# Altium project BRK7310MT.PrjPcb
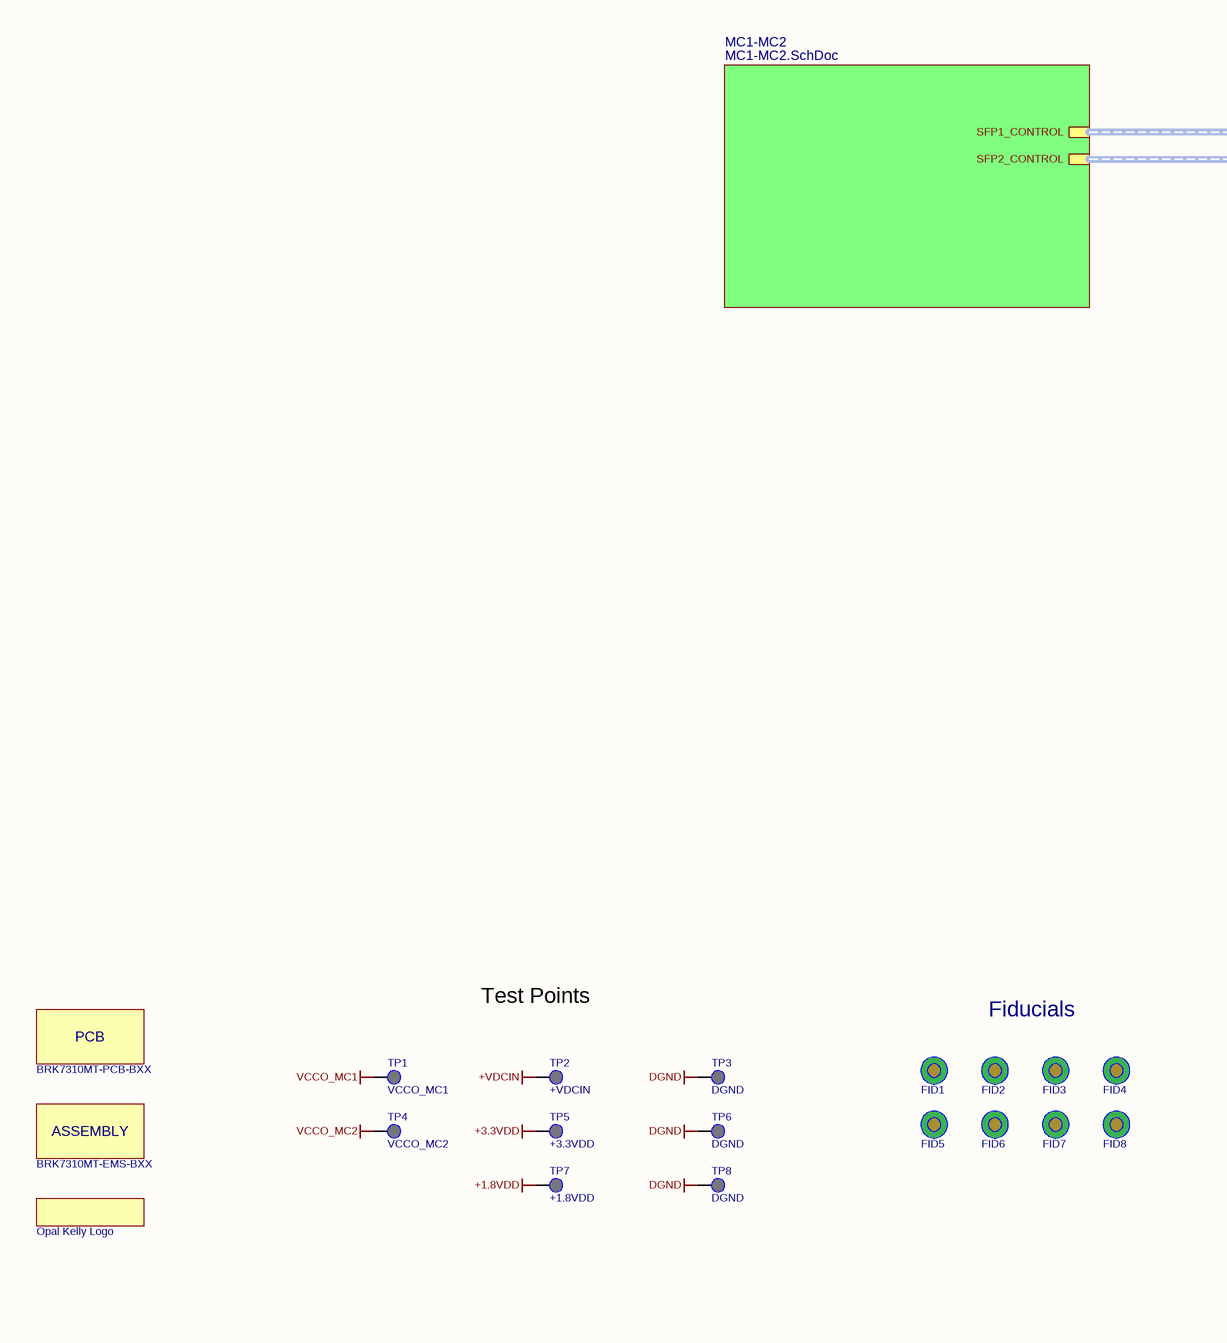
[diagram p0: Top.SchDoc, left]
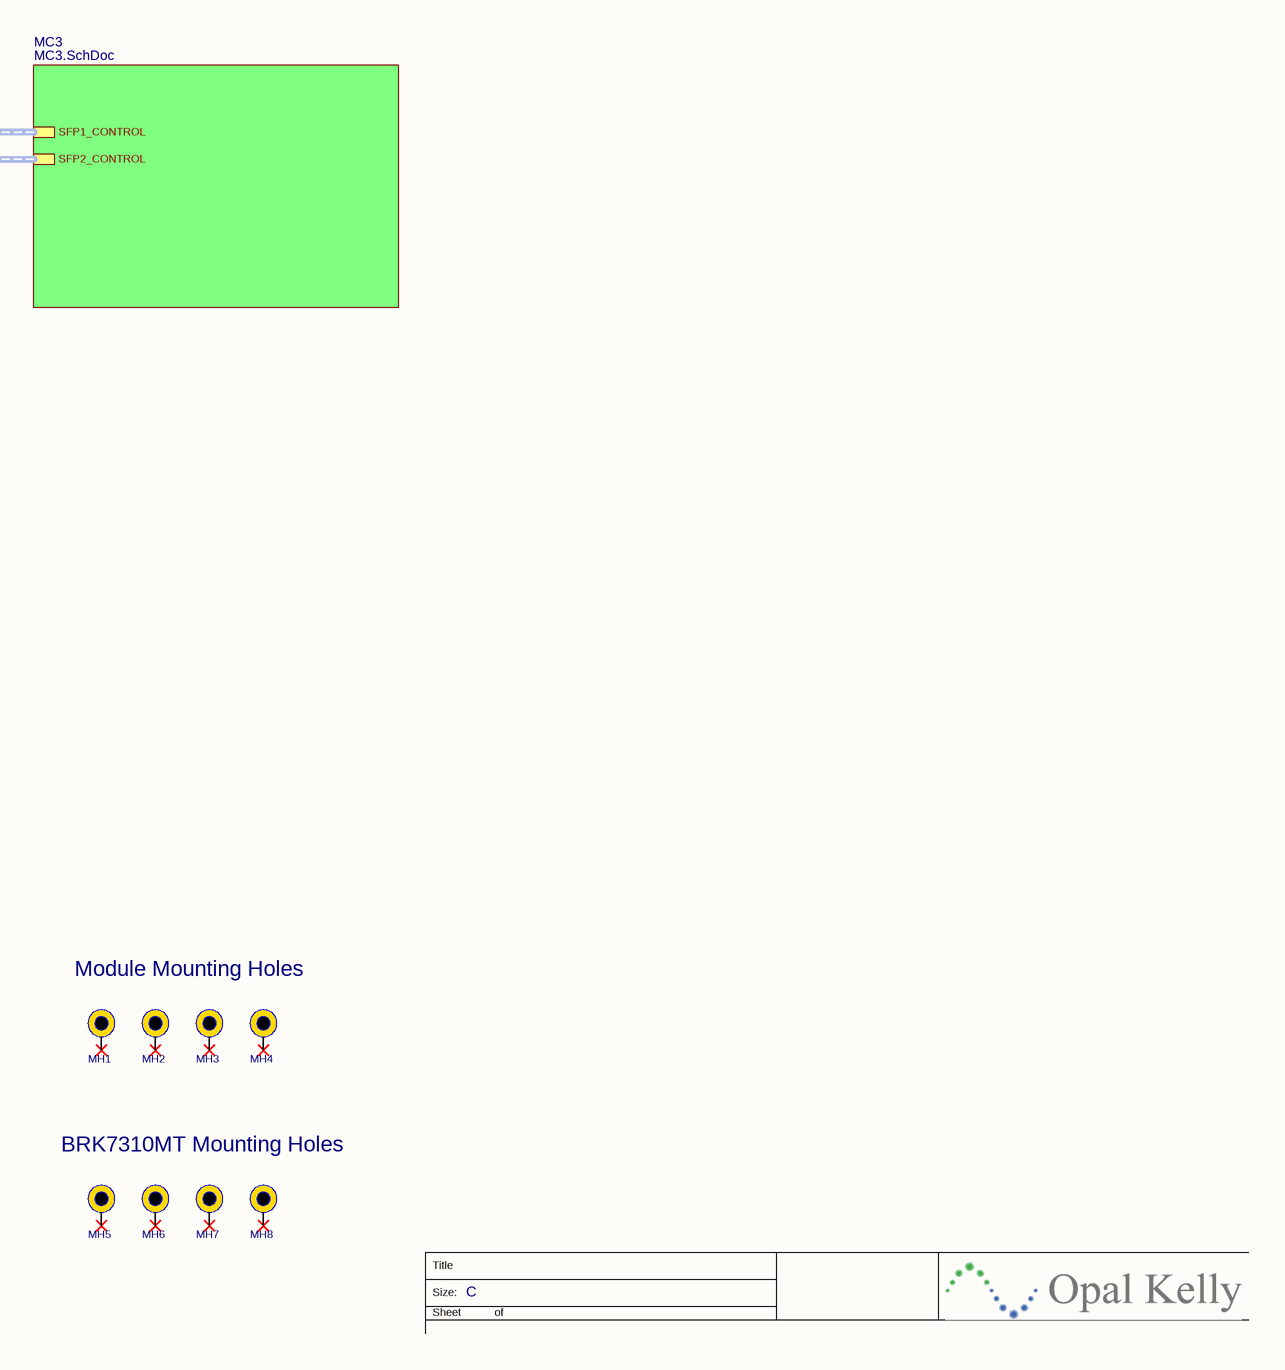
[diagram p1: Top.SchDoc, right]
BOM_Revision: 01; Part_Number: BRK7310MT; PCB_Date_Code: 20181221; PCB_Revision: B; VariantBoms: Default=001770
3 sheets, 81 parts. Net scope: hierarchical (ports join the sheet entries above them; power ports are global).
Board file: BRK7310MT.PcbDoc
Sheets:
  Top.SchDoc
    MC1-MC2 = MC1-MC2.SchDoc
    MC3 = MC3.SchDoc

## Sheet Top.SchDoc: BRK7310MT - Top Level
size C; Organization: Opal Kelly; Address1: 13500 SW 72nd Ave STE 100; Address3: Portland, OR  97223; Address4: http://www.opalkelly.com; DocumentNumber: xxx; Revision: 1; SheetNumber: 1; SheetTotal: 3; PageSetup: Record=PageOptions¦CenterHorizontal=True¦CenterVertical=True¦PrintScale=0.52¦XCorrection=1.00¦YCorrection=1.00¦PrintKind=0¦BorderSize=5000000¦LeftOffset=0¦BottomOffset=0¦Orientation=2¦PaperLength=1000¦PaperWidth=1000¦Scale=100¦PaperSource=15¦PrintQuality=600¦MediaType=1¦DitherType=10¦PaperKind=Letter¦PrintScaleMode=1

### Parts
*1  Opal Kelly Logo  [okLogo-23x5]
ASSY1  BRK7310MT-EMS-BXX  (mechanical)
FID1  FIDUCIAL  [FID1MM/2MM-SS]  (value not drawn)
FID2  FIDUCIAL  [FID1MM/2MM-SS]  (value not drawn)
FID3  FIDUCIAL  [FID1MM/2MM-SS]  (value not drawn)
FID4  FIDUCIAL  [FID1MM/2MM-SS]  (value not drawn)
FID5  FIDUCIAL  [FID1MM/2MM-SS]  (value not drawn)
FID6  FIDUCIAL  [FID1MM/2MM-SS]  (value not drawn)
FID7  FIDUCIAL  [FID1MM/2MM-SS]  (value not drawn)
FID8  FIDUCIAL  [FID1MM/2MM-SS]  (value not drawn)
MH1  MTG  [MTG-3.2/6.5-PTH]  (value not drawn)
MH2  MTG  [MTG-3.2/6.5-PTH]  (value not drawn)
MH3  MTG  [MTG-3.2/6.5-PTH]  (value not drawn)
MH4  MTG  [MTG-3.2/6.5-PTH]  (value not drawn)
MH5  MTG  [MTG-2.7/5.0-PTH]  (value not drawn)
MH6  MTG  [MTG-2.7/5.0-PTH]  (value not drawn)
MH7  MTG  [MTG-2.7/5.0-PTH]  (value not drawn)
MH8  MTG  [MTG-2.7/5.0-PTH]  (value not drawn)
PCB1  BRK7310MT-PCB-BXX  (mechanical)
TP1  VCCO_MC1  [TP-PTH-65/100]
TP2  +VDCIN  [TP-PTH-65/100]
TP3  DGND  [TP-PTH-65/100]
TP4  VCCO_MC2  [TP-PTH-65/100]
TP5  +3.3VDD  [TP-PTH-65/100]
TP6  DGND  [TP-PTH-65/100]
TP7  +1.8VDD  [TP-PTH-65/100]
TP8  DGND  [TP-PTH-65/100]

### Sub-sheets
MC1-MC2 = MC1-MC2.SchDoc: SFP1_CONTROL (harness SFP_Control), SFP2_CONTROL (harness SFP_Control)
MC3 = MC3.SchDoc: SFP1_CONTROL (harness SFP_Control), SFP2_CONTROL (harness SFP_Control)

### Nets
+1.8VDD: TP7.1(PIN)
+3.3VDD: TP5.1(PIN)
+VDCIN: TP2.1(PIN)
DGND: TP3.1(PIN) TP6.1(PIN) TP8.1(PIN)
VCCO_MC1: TP1.1(PIN)
VCCO_MC2: TP4.1(PIN)

Not connected (* = marked no-connect by the designer): MH1 1*; MH2 1*; MH3 1*; MH4 1*; MH5 1*; MH6 1*; MH7 1*; MH8 1*

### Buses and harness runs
harness sheet MC1-MC2/SFP1_CONTROL = sheet MC3/SFP1_CONTROL
harness sheet MC1-MC2/SFP2_CONTROL = sheet MC3/SFP2_CONTROL

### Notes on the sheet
- Module Mounting Holes
- Test Points
- Fiducials
- BRK7310MT Mounting Holes
- Title
- Size:
- Sheet
- C
- of

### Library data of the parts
*1 = OKLOGO
ASSY1 = ASSEMBLY: BRK7310MT PCB assembly; Manufacturer: PCB Assembly Cost; partnumber: 001841
FID1-FID8 = FIDUCIAL: PCB fiducial
MH1-MH8 = MTG: Mounting hole
PCB1 = PCB: PCB for BRK7310MT; Manufacturer: Generic PCB Manufacturer; partnumber: 001842
TP1-TP8 = TP-PTH-65/100: Test point, plated through-hole, 65/100mil

## Sheet MC1-MC2.SchDoc: BRK7310MT - MC1, MC2
size C; Author: Casey Smith; Organization: Opal Kelly; Address1: 13500 SW 72nd Ave, STE 205; Address2: Portland, OR 97223; Address3: 217.391.3724; Address4: http://www.opalkelly.com; DocumentNumber: xxx; Revision: 1; SheetNumber: 2; SheetTotal: 3
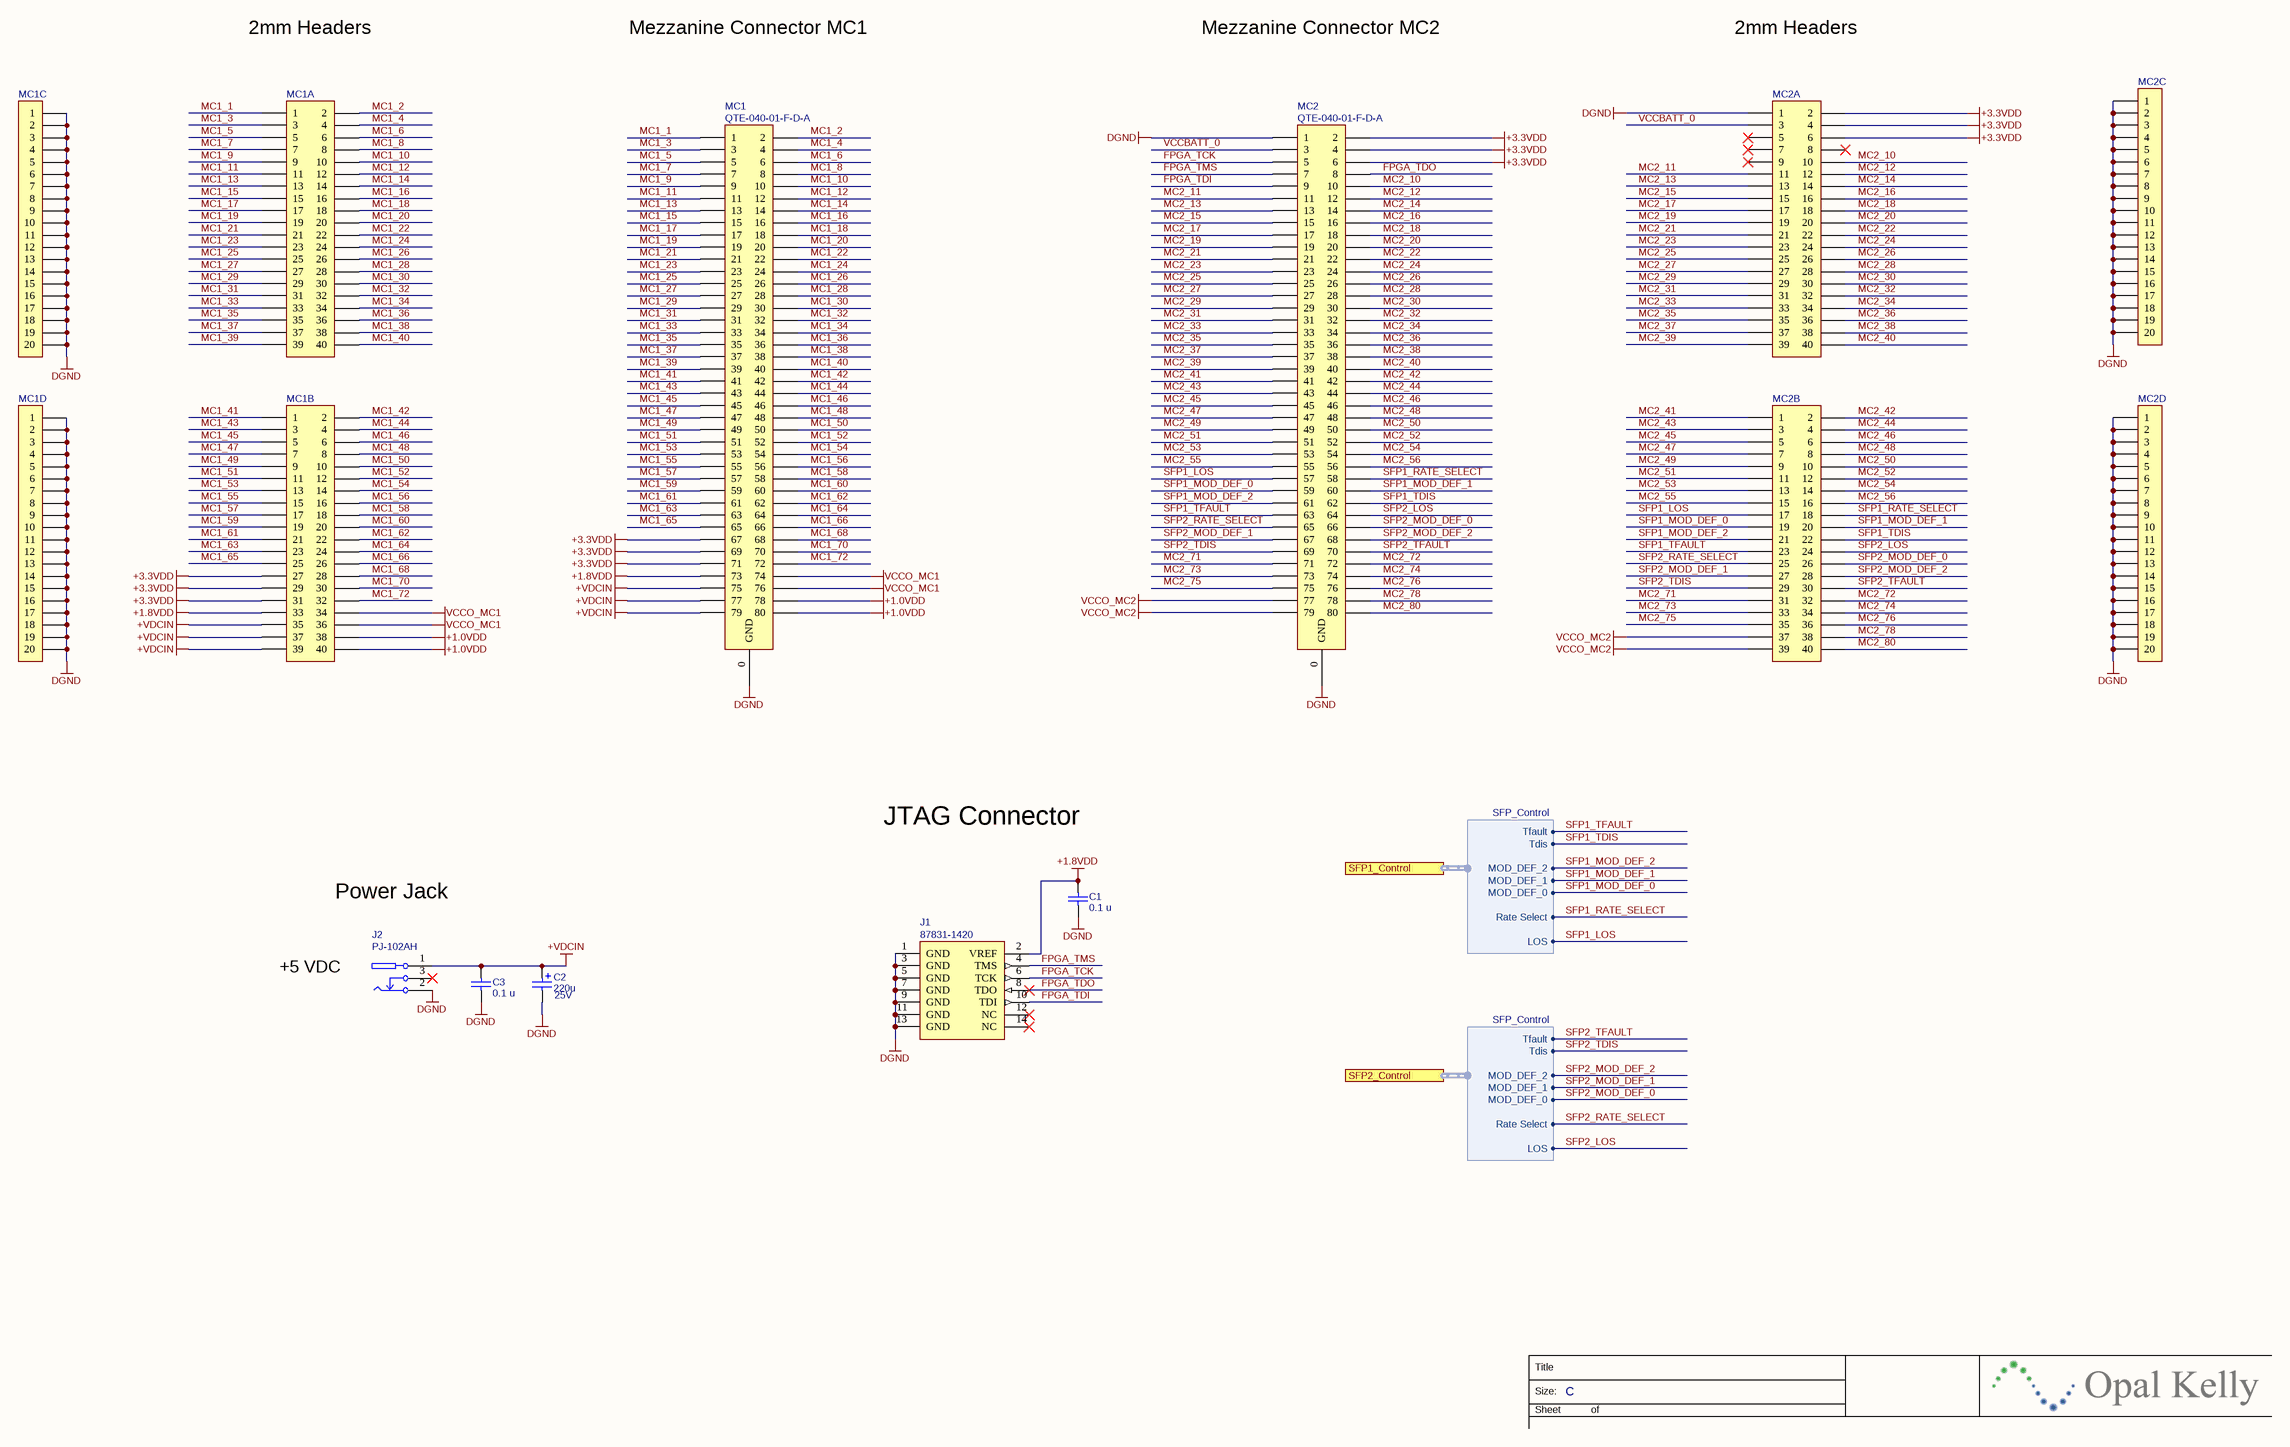
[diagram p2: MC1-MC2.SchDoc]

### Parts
C1  value 0.1 u  [CAPC1005X06A]  (hidden comment: SM-0402, 10%, 10v)
C2  value 220u  Voltage: 25V  [CAPAE9083X70N]  (hidden comment: EEE-FK1E221P)
C3  value 0.1 u  [CAPC1005X06A]  (hidden comment: TMK105BJ104KV-F)
J1  87831-1420  [XILINX-JTAG]
J2  PJ-102AH  [CUI-PJ102A]
MC1  QTE-040-01-F-D-A  [QTE-040-01-X-D-A]
MC1A  0877584016  [HDR2X20-2MM]  (value not drawn)
MC1B  0877584016  [HDR2X20-2MM]  (value not drawn)
MC1C  Header, 20-Pin, Single Row  [HDR1X20-2MM]  (value not drawn)
MC1D  Header, 20-Pin, Single Row  [HDR1X20-2MM]  (value not drawn)
MC2  QTE-040-01-F-D-A  [QTE-040-01-X-D-A]
MC2A  0877584016  [HDR2X20-2MM]  (value not drawn)
MC2B  0877584016  [HDR2X20-2MM]  (value not drawn)
MC2C  Header, 20-Pin, Single Row  [HDR1X20-2MM]  (value not drawn)
MC2D  Header, 20-Pin, Single Row  [HDR1X20-2MM]  (value not drawn)

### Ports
SFP1_Control (harness SFP_Control), SFP2_Control (harness SFP_Control)

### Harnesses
SFP_Control: Tfault, MOD_DEF_0, MOD_DEF_1, MOD_DEF_2, Tdis, Rate Select, LOS

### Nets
+1.0VDD: MC1.78 MC1.80 MC1B.38 MC1B.40
+1.8VDD: C1.2 J1.2(VREF) MC1.73 MC1B.33
+3.3VDD: MC1.67 MC1.69 MC1.71 MC1B.27 MC1B.29 MC1B.31 MC2.2 MC2.4 MC2.6 MC2A.2 MC2A.4 MC2A.6
+VDCIN: C2.1 C3.2 J2.1 MC1.75 MC1.77 MC1.79 MC1B.35 MC1B.37 MC1B.39
DGND: C1.1 C2.2 C3.1 J1.1(GND) J1.3(GND) J1.5(GND) J1.7(GND) J1.9(GND) J1.11(GND) J1.13(GND) J2.2 MC1.0(GND) MC1C.1 MC1C.2 MC1C.3 MC1C.4 MC1C.5 MC1C.6 MC1C.7 MC1C.8 MC1C.9 MC1C.10 MC1C.11 MC1C.12 MC1C.13 MC1C.14 MC1C.15 MC1C.16 MC1C.17 MC1C.18 MC1C.19 MC1C.20 MC1D.1 MC1D.2 MC1D.3 MC1D.4 MC1D.5 MC1D.6 MC1D.7 MC1D.8 MC1D.9 MC1D.10 MC1D.11 MC1D.12 MC1D.13 MC1D.14 MC1D.15 MC1D.16 MC1D.17 MC1D.18 MC1D.19 MC1D.20 MC2.0(GND) MC2.1 MC2A.1 MC2C.1 MC2C.2 MC2C.3 MC2C.4 MC2C.5 MC2C.6 MC2C.7 MC2C.8 MC2C.9 MC2C.10 MC2C.11 MC2C.12 MC2C.13 MC2C.14 MC2C.15 MC2C.16 MC2C.17 MC2C.18 MC2C.19 MC2C.20 MC2D.1 MC2D.2 MC2D.3 MC2D.4 MC2D.5 MC2D.6 MC2D.7 MC2D.8 MC2D.9 MC2D.10 MC2D.11 MC2D.12 MC2D.13 MC2D.14 MC2D.15 MC2D.16 MC2D.17 MC2D.18 MC2D.19 MC2D.20
VCCO_MC1: MC1.74 MC1.76 MC1B.34 MC1B.36
VCCO_MC2: MC2.77 MC2.79 MC2B.37 MC2B.39
FPGA_TCK: J1.6(TCK) MC2.5
FPGA_TDI: J1.10(TDI) MC2.9
FPGA_TDO: J1.8(TDO) MC2.8
FPGA_TMS: J1.4(TMS) MC2.7
MC1_1: MC1.1 MC1A.1
MC1_2: MC1.2 MC1A.2
MC1_3: MC1.3 MC1A.3
MC1_4: MC1.4 MC1A.4
MC1_5: MC1.5 MC1A.5
MC1_6: MC1.6 MC1A.6
MC1_7: MC1.7 MC1A.7
MC1_8: MC1.8 MC1A.8
MC1_9: MC1.9 MC1A.9
MC1_10: MC1.10 MC1A.10
MC1_11: MC1.11 MC1A.11
MC1_12: MC1.12 MC1A.12
MC1_13: MC1.13 MC1A.13
MC1_14: MC1.14 MC1A.14
MC1_15: MC1.15 MC1A.15
MC1_16: MC1.16 MC1A.16
MC1_17: MC1.17 MC1A.17
MC1_18: MC1.18 MC1A.18
MC1_19: MC1.19 MC1A.19
MC1_20: MC1.20 MC1A.20
MC1_21: MC1.21 MC1A.21
MC1_22: MC1.22 MC1A.22
MC1_23: MC1.23 MC1A.23
MC1_24: MC1.24 MC1A.24
MC1_25: MC1.25 MC1A.25
MC1_26: MC1.26 MC1A.26
MC1_27: MC1.27 MC1A.27
MC1_28: MC1.28 MC1A.28
MC1_29: MC1.29 MC1A.29
MC1_30: MC1.30 MC1A.30
MC1_31: MC1.31 MC1A.31
MC1_32: MC1.32 MC1A.32
MC1_33: MC1.33 MC1A.33
MC1_34: MC1.34 MC1A.34
MC1_35: MC1.35 MC1A.35
MC1_36: MC1.36 MC1A.36
MC1_37: MC1.37 MC1A.37
MC1_38: MC1.38 MC1A.38
MC1_39: MC1.39 MC1A.39
MC1_40: MC1.40 MC1A.40
MC1_41: MC1.41 MC1B.1
MC1_42: MC1.42 MC1B.2
MC1_43: MC1.43 MC1B.3
MC1_44: MC1.44 MC1B.4
MC1_45: MC1.45 MC1B.5
MC1_46: MC1.46 MC1B.6
MC1_47: MC1.47 MC1B.7
MC1_48: MC1.48 MC1B.8
MC1_49: MC1.49 MC1B.9
MC1_50: MC1.50 MC1B.10
MC1_51: MC1.51 MC1B.11
MC1_52: MC1.52 MC1B.12
MC1_53: MC1.53 MC1B.13
MC1_54: MC1.54 MC1B.14
MC1_55: MC1.55 MC1B.15
MC1_56: MC1.56 MC1B.16
MC1_57: MC1.57 MC1B.17
MC1_58: MC1.58 MC1B.18
MC1_59: MC1.59 MC1B.19
MC1_60: MC1.60 MC1B.20
MC1_61: MC1.61 MC1B.21
MC1_62: MC1.62 MC1B.22
MC1_63: MC1.63 MC1B.23
MC1_64: MC1.64 MC1B.24
MC1_65: MC1.65 MC1B.25
MC1_66: MC1.66 MC1B.26
MC1_68: MC1.68 MC1B.28
MC1_70: MC1.70 MC1B.30
MC1_72: MC1.72 MC1B.32
MC2_10: MC2.10 MC2A.10
MC2_11: MC2.11 MC2A.11
MC2_12: MC2.12 MC2A.12
MC2_13: MC2.13 MC2A.13
MC2_14: MC2.14 MC2A.14
MC2_15: MC2.15 MC2A.15
MC2_16: MC2.16 MC2A.16
MC2_17: MC2.17 MC2A.17
MC2_18: MC2.18 MC2A.18
MC2_19: MC2.19 MC2A.19
MC2_20: MC2.20 MC2A.20
MC2_21: MC2.21 MC2A.21
MC2_22: MC2.22 MC2A.22
MC2_23: MC2.23 MC2A.23
MC2_24: MC2.24 MC2A.24
MC2_25: MC2.25 MC2A.25
MC2_26: MC2.26 MC2A.26
MC2_27: MC2.27 MC2A.27
MC2_28: MC2.28 MC2A.28
MC2_29: MC2.29 MC2A.29
MC2_30: MC2.30 MC2A.30
MC2_31: MC2.31 MC2A.31
MC2_32: MC2.32 MC2A.32
MC2_33: MC2.33 MC2A.33
MC2_34: MC2.34 MC2A.34
MC2_35: MC2.35 MC2A.35
MC2_36: MC2.36 MC2A.36
MC2_37: MC2.37 MC2A.37
MC2_38: MC2.38 MC2A.38
MC2_39: MC2.39 MC2A.39
MC2_40: MC2.40 MC2A.40
MC2_41: MC2.41 MC2B.1
MC2_42: MC2.42 MC2B.2
MC2_43: MC2.43 MC2B.3
MC2_44: MC2.44 MC2B.4
MC2_45: MC2.45 MC2B.5
MC2_46: MC2.46 MC2B.6
MC2_47: MC2.47 MC2B.7
MC2_48: MC2.48 MC2B.8
MC2_49: MC2.49 MC2B.9
MC2_50: MC2.50 MC2B.10
MC2_51: MC2.51 MC2B.11
MC2_52: MC2.52 MC2B.12
MC2_53: MC2.53 MC2B.13
MC2_54: MC2.54 MC2B.14
MC2_55: MC2.55 MC2B.15
MC2_56: MC2.56 MC2B.16
MC2_71: MC2.71 MC2B.31
MC2_72: MC2.72 MC2B.32
MC2_73: MC2.73 MC2B.33
MC2_74: MC2.74 MC2B.34
MC2_75: MC2.75 MC2B.35
MC2_76: MC2.76 MC2B.36
MC2_78: MC2.78 MC2B.38
MC2_80: MC2.80 MC2B.40
SFP1_LOS: MC2.57 MC2B.17 ; port SFP1_Control.LOS
SFP1_MOD_DEF_0: MC2.59 MC2B.19 ; port SFP1_Control.MOD_DEF_0
SFP1_MOD_DEF_1: MC2.60 MC2B.20 ; port SFP1_Control.MOD_DEF_1
SFP1_MOD_DEF_2: MC2.61 MC2B.21 ; port SFP1_Control.MOD_DEF_2
SFP1_RATE_SELECT: MC2.58 MC2B.18 ; port SFP1_Control.Rate Select
SFP1_TDIS: MC2.62 MC2B.22 ; port SFP1_Control.Tdis
SFP1_TFAULT: MC2.63 MC2B.23 ; port SFP1_Control.Tfault
SFP2_LOS: MC2.64 MC2B.24 ; port SFP2_Control.LOS
SFP2_MOD_DEF_0: MC2.66 MC2B.26 ; port SFP2_Control.MOD_DEF_0
SFP2_MOD_DEF_1: MC2.67 MC2B.27 ; port SFP2_Control.MOD_DEF_1
SFP2_MOD_DEF_2: MC2.68 MC2B.28 ; port SFP2_Control.MOD_DEF_2
SFP2_RATE_SELECT: MC2.65 MC2B.25 ; port SFP2_Control.Rate Select
SFP2_TDIS: MC2.69 MC2B.29 ; port SFP2_Control.Tdis
SFP2_TFAULT: MC2.70 MC2B.30 ; port SFP2_Control.Tfault
VCCBATT_0: MC2.3 MC2A.3

Not connected (* = marked no-connect by the designer): J1 12(NC)* 14(NC)*; J2 3*; MC2A 5* 7* 8* 9*

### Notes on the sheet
- 2mm Headers
- Mezzanine Connector MC1
- Mezzanine Connector MC2
- JTAG Connector
- Power Jack
- +5 VDC
- Title
- Size:
- Sheet
- C
- of

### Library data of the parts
C1 = 000070: Partnumber: 000070; manufacturer: Kemet; manufacturer_pn: C0402C104K8PACTU; ValueFloat: 1E-7; id: 750; inventory_price: 0.0023; reorder_quantity: 70000; x_tolerance: 10
C2 = 001532: Polarized; Partnumber: 001532; manufacturer: Panasonic; ValueFloat: 0.00022; id: 155442; inventory_price: 0.2; x_tolerance: 20; x_voltage-rating: 25
C3 = 001073: Ceramic capacitor; Manufacturer: Taiyo Yuden; partnumber: 001073; Description 2: 0402, 25V; ValueFloat: 1E-7; Tolerance (%): 10; Voltage: 25V
J1 = 000541: 2mm header, shrouded; Manufacturer: Molex; partnumber: 000541; Description 2: Dual-row, 14-pos, Xilinx JTAG compatible
J2 = 000356: DC power connector - high current; Manufacturer: CUI Inc.; partnumber: 000356; Description 2: 2.1mm / 5.5mm
MC1 MC2 = QTE_QSE-040: 0.8mm hi-speed, high-density header (female); Manufacturer: Samtec; partnumber: 000972
MC1A MC1B = Header 20X2: 2mm header, 20x2, thru-hole; Manufacturer: Molex; partnumber: 000583
MC1C MC1D = Header 1X20: 2mm header, 20x1, thru-hole; PartNumber: 001334; Manufacturer: 3M; Manufacturer_PN: 951120-8622-AR
MC2A MC2B = 000583: Partnumber: 000583; manufacturer: Molex; id: 9990; inventory_price: 1.03
MC2C MC2D = 001334: PartNumber: 001334; manufacturer: 3M; manufacturer_pn: 951120-8622-AR; id: 98023; inventory_price: 0.924

## Sheet MC3.SchDoc: BRK7310MT - MC3
size C; Author: Casey Smith; Organization: Opal Kelly; Address1: 13500 SW 72nd Ave, STE 205; Address2: Portland, OR 97223; Address3: 217.391.3724; Address4: http://www.opalkelly.com; DocumentNumber: xxx; Revision: 1; SheetNumber: 3; SheetTotal: 3
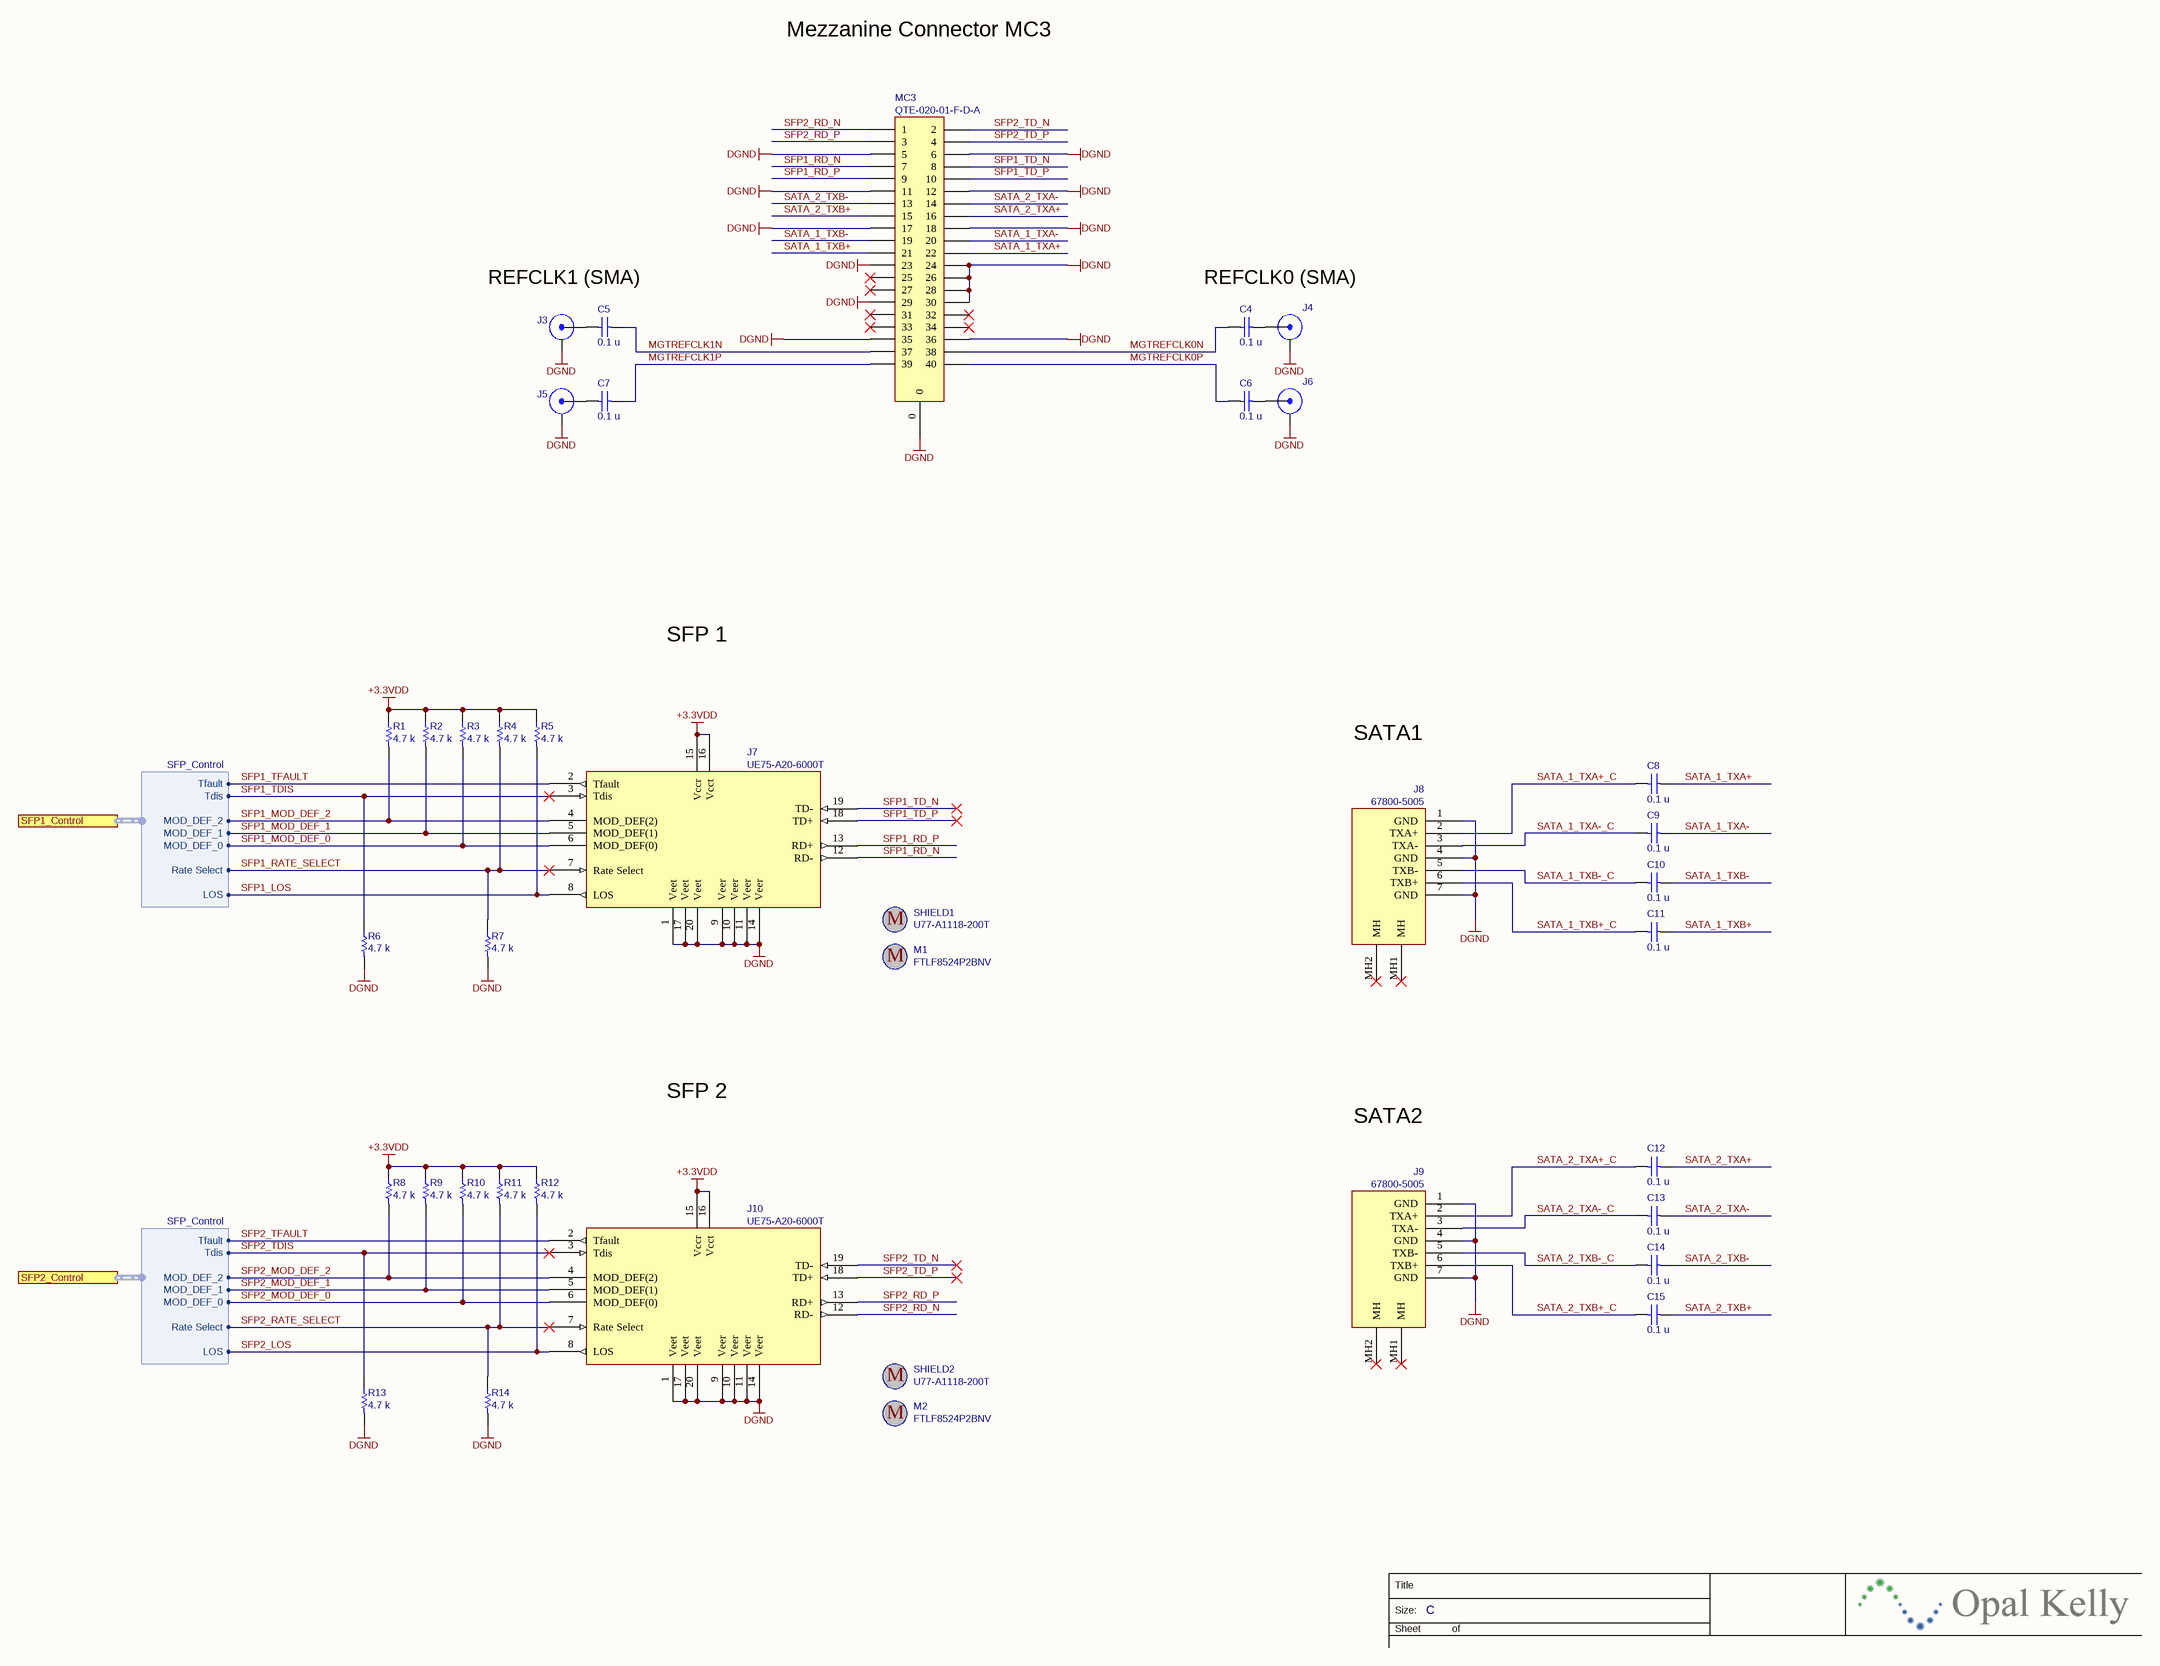
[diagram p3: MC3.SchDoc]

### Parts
C4  value 0.1 u  [CAPC1005X06A]  (hidden comment: SM-0402, 10%, 10v)
C5  value 0.1 u  [CAPC1005X06A]  (hidden comment: SM-0402, 10%, 10v)
C6  value 0.1 u  [CAPC1005X06A]  (hidden comment: SM-0402, 10%, 10v)
C7  value 0.1 u  [CAPC1005X06A]  (hidden comment: SM-0402, 10%, 10v)
C8  value 0.1 u  [CAPC1005X06A]  (hidden comment: SM-0402, 10%, 10v)
C9  value 0.1 u  [CAPC1005X06A]  (hidden comment: SM-0402, 10%, 10v)
C10  value 0.1 u  [CAPC1005X06A]  (hidden comment: SM-0402, 10%, 10v)
C11  value 0.1 u  [CAPC1005X06A]  (hidden comment: SM-0402, 10%, 10v)
C12  value 0.1 u  [CAPC1005X06A]  (hidden comment: SM-0402, 10%, 10v)
C13  value 0.1 u  [CAPC1005X06A]  (hidden comment: SM-0402, 10%, 10v)
C14  value 0.1 u  [CAPC1005X06A]  (hidden comment: SM-0402, 10%, 10v)
C15  value 0.1 u  [CAPC1005X06A]  (hidden comment: SM-0402, 10%, 10v)
J3  REFCLK1n  [SMA]  (value not drawn)
J4  REFCLK0n  [SMA]  (value not drawn)
J5  REFCLK1p  [SMA]  (value not drawn)
J6  REFCLK0p  [SMA]  (value not drawn)
J7  UE75-A20-6000T  [SFP_RCPT_20_CAGE]
J8  67800-5005  [MOLEX-67800-5005]
J9  67800-5005  [MOLEX-67800-5005]
J10  UE75-A20-6000T  [SFP_RCPT_20_CAGE]
M1  FTLF8524P2BNV  (mechanical)
M2  FTLF8524P2BNV  (mechanical)
MC3  QTE-020-01-F-D-A  [QTE-020-01-X-D-A]
R1  value 4.7 k  [RESC1005X06A]  (hidden comment: CRCW04024K70JNED)
R2  value 4.7 k  [RESC1005X06A]  (hidden comment: CRCW04024K70JNED)
R3  value 4.7 k  [RESC1005X06A]  (hidden comment: CRCW04024K70JNED)
R4  value 4.7 k  [RESC1005X06A]  (hidden comment: CRCW04024K70JNED)
R5  value 4.7 k  [RESC1005X06A]  (hidden comment: CRCW04024K70JNED)
R6  value 4.7 k  [RESC1005X06A]  (hidden comment: CRCW04024K70JNED)
R7  value 4.7 k  [RESC1005X06A]  (hidden comment: CRCW04024K70JNED)
R8  value 4.7 k  [RESC1005X06A]  (hidden comment: CRCW04024K70JNED)
R9  value 4.7 k  [RESC1005X06A]  (hidden comment: CRCW04024K70JNED)
R10  value 4.7 k  [RESC1005X06A]  (hidden comment: CRCW04024K70JNED)
R11  value 4.7 k  [RESC1005X06A]  (hidden comment: CRCW04024K70JNED)
R12  value 4.7 k  [RESC1005X06A]  (hidden comment: CRCW04024K70JNED)
R13  value 4.7 k  [RESC1005X06A]  (hidden comment: CRCW04024K70JNED)
R14  value 4.7 k  [RESC1005X06A]  (hidden comment: CRCW04024K70JNED)
SHIELD1  U77-A1118-200T  (mechanical)
SHIELD2  U77-A1118-200T  (mechanical)

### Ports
SFP1_Control (harness SFP_Control), SFP2_Control (harness SFP_Control)

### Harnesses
SFP_Control: Tfault, MOD_DEF_0, MOD_DEF_1, MOD_DEF_2, Tdis, Rate Select, LOS

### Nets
+3.3VDD: J7.15(Vccr) J7.16(Vcct) J10.15(Vccr) J10.16(Vcct) R1.1 R2.1 R3.1 R4.1 R5.1 R8.1 R9.1 R10.1 R11.1 R12.1
DGND: J3.2(GND) J4.2(GND) J5.2(GND) J6.2(GND) J7.1(Veet) J7.9(Veer) J7.10(Veer) J7.11(Veer) J7.14(Veer) J7.17(Veet) J7.20(Veet) J8.1(GND) J8.4(GND) J8.7(GND) J9.1(GND) J9.4(GND) J9.7(GND) J10.1(Veet) J10.9(Veer) J10.10(Veer) J10.11(Veer) J10.14(Veer) J10.17(Veet) J10.20(Veet) MC3.0 MC3.5 MC3.6 MC3.11 MC3.12 MC3.17 MC3.18 MC3.23 MC3.24 MC3.26 MC3.28 MC3.29 MC3.30 MC3.35 MC3.36 R6.2 R7.2 R13.2 R14.2
MGTREFCLK0N: C4.2 MC3.38
MGTREFCLK0P: C6.2 MC3.40
MGTREFCLK1N: C5.2 MC3.37
MGTREFCLK1P: C7.2 MC3.39
SATA_1_TXA+: C8.2 MC3.22
SATA_1_TXA+_C: C8.1 J8.2(TXA+)
SATA_1_TXA-: C9.2 MC3.20
SATA_1_TXA-_C: C9.1 J8.3(TXA-)
SATA_1_TXB+: C11.2 MC3.21
SATA_1_TXB+_C: C11.1 J8.6(TXB+)
SATA_1_TXB-: C10.2 MC3.19
SATA_1_TXB-_C: C10.1 J8.5(TXB-)
SATA_2_TXA+: C12.2 MC3.16
SATA_2_TXA+_C: C12.1 J9.2(TXA+)
SATA_2_TXA-: C13.2 MC3.14
SATA_2_TXA-_C: C13.1 J9.3(TXA-)
SATA_2_TXB+: C15.2 MC3.15
SATA_2_TXB+_C: C15.1 J9.6(TXB+)
SATA_2_TXB-: C14.2 MC3.13
SATA_2_TXB-_C: C14.1 J9.5(TXB-)
SFP1_LOS: J7.8(LOS) R5.2 ; port SFP1_Control.LOS
SFP1_MOD_DEF_0: J7.6(MOD_DEF(0)) R3.2 ; port SFP1_Control.MOD_DEF_0
SFP1_MOD_DEF_1: J7.5(MOD_DEF(1)) R2.2 ; port SFP1_Control.MOD_DEF_1
SFP1_MOD_DEF_2: J7.4(MOD_DEF(2)) R1.2 ; port SFP1_Control.MOD_DEF_2
SFP1_RATE_SELECT: J7.7(Rate_Select) R4.2 R7.1 ; port SFP1_Control.Rate Select
SFP1_RD_N: J7.12(RD-) MC3.7
SFP1_RD_P: J7.13(RD+) MC3.9
SFP1_TD_N: J7.19(TD-) MC3.8
SFP1_TD_P: J7.18(TD+) MC3.10
SFP1_TDIS: J7.3(Tdis) R6.1 ; port SFP1_Control.Tdis
SFP1_TFAULT: J7.2(Tfault) ; port SFP1_Control.Tfault
SFP2_LOS: J10.8(LOS) R12.2 ; port SFP2_Control.LOS
SFP2_MOD_DEF_0: J10.6(MOD_DEF(0)) R10.2 ; port SFP2_Control.MOD_DEF_0
SFP2_MOD_DEF_1: J10.5(MOD_DEF(1)) R9.2 ; port SFP2_Control.MOD_DEF_1
SFP2_MOD_DEF_2: J10.4(MOD_DEF(2)) R8.2 ; port SFP2_Control.MOD_DEF_2
SFP2_RATE_SELECT: J10.7(Rate_Select) R11.2 R14.1 ; port SFP2_Control.Rate Select
SFP2_RD_N: J10.12(RD-) MC3.1
SFP2_RD_P: J10.13(RD+) MC3.3
SFP2_TD_N: J10.19(TD-) MC3.2
SFP2_TD_P: J10.18(TD+) MC3.4
SFP2_TDIS: J10.3(Tdis) R13.1 ; port SFP2_Control.Tdis
SFP2_TFAULT: J10.2(Tfault) ; port SFP2_Control.Tfault
NetC4_1: C4.1 J4.1(SIGNAL)
NetC5_1: C5.1 J3.1(SIGNAL)
NetC6_1: C6.1 J6.1(SIGNAL)
NetC7_1: C7.1 J5.1(SIGNAL)

Not connected (* = marked no-connect by the designer): J8 MH1(MH)* MH2(MH)*; J9 MH1(MH)* MH2(MH)*; MC3 25* 27* 31* 32* 33* 34*

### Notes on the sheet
- Mezzanine Connector MC3
- REFCLK1 (SMA)
- REFCLK0 (SMA)
- SFP 1
- SATA1
- SFP 2
- SATA2
- Title
- Size:
- Sheet
- C
- of

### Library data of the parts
C4-C15 = 000070: as C1 on sheet MC1-MC2
J3-J6 = 000974: Straight SMA PCB Mount; Manufacturer: Amphenol; Manufacturer_PN: 901-144-8RFX; partnumber: 000974
J7 J10 = 000986: SFP 20-POS Recepticle; Manufacturer: Amphenol; partnumber: 000986; Description 2: Right Angle, SMD, 15AU Gold
J8 J9 = 000988: SATA 7-pin receptacle; Manufacturer: Molex; partnumber: 000988; Description 2: Vertical Mount, SMD, Latch, 15u Gold; x_lifecycle_status: Production
M1 M2 = 000985: SFP Transceiver; Manufacturer: Finisar; partnumber: 000985; Description 2: 4.25Gb/s, Narrow Extraction Bail, Rate Selectable
MC3 = QTE_QSE-020: 0.8mm hi-speed, high-density header (female); Manufacturer: Samtec; partnumber: 000973
R1-R14 = Resistor: Thick-film resistor; Manufacturer: Vishay; partnumber: 000754; ValueFloat: 4700.0
SHIELD1 SHIELD2 = 000987: SFP Single Cage; Manufacturer: Amphenol; partnumber: 000987; Description 2: Pressfit; x_lifecycle_status: Production

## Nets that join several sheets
+1.8VDD: Top (TP7.1), MC1-MC2 (C1.2 J1.2 MC1.73 MC1B.33)
+3.3VDD: Top (TP5.1), MC1-MC2 (12 pins), MC3 (14 pins)
+VDCIN: Top (TP2.1), MC1-MC2 (9 pins)
DGND: Top (TP3.1 TP6.1 TP8.1), MC1-MC2 (95 pins), MC3 (43 pins)
VCCO_MC1: Top (TP1.1), MC1-MC2 (MC1.74 MC1.76 MC1B.34 MC1B.36)
VCCO_MC2: Top (TP4.1), MC1-MC2 (MC2.77 MC2.79 MC2B.37 MC2B.39)
SFP1_LOS: MC1-MC2 (MC2.57 MC2B.17), MC3 (J7.8 R5.2)
SFP1_MOD_DEF_0: MC1-MC2 (MC2.59 MC2B.19), MC3 (J7.6 R3.2)
SFP1_MOD_DEF_1: MC1-MC2 (MC2.60 MC2B.20), MC3 (J7.5 R2.2)
SFP1_MOD_DEF_2: MC1-MC2 (MC2.61 MC2B.21), MC3 (J7.4 R1.2)
SFP1_RATE_SELECT: MC1-MC2 (MC2.58 MC2B.18), MC3 (J7.7 R4.2 R7.1)
SFP1_TDIS: MC1-MC2 (MC2.62 MC2B.22), MC3 (J7.3 R6.1)
SFP1_TFAULT: MC1-MC2 (MC2.63 MC2B.23), MC3 (J7.2)
SFP2_LOS: MC1-MC2 (MC2.64 MC2B.24), MC3 (J10.8 R12.2)
SFP2_MOD_DEF_0: MC1-MC2 (MC2.66 MC2B.26), MC3 (J10.6 R10.2)
SFP2_MOD_DEF_1: MC1-MC2 (MC2.67 MC2B.27), MC3 (J10.5 R9.2)
SFP2_MOD_DEF_2: MC1-MC2 (MC2.68 MC2B.28), MC3 (J10.4 R8.2)
SFP2_RATE_SELECT: MC1-MC2 (MC2.65 MC2B.25), MC3 (J10.7 R11.2 R14.1)
SFP2_TDIS: MC1-MC2 (MC2.69 MC2B.29), MC3 (J10.3 R13.1)
SFP2_TFAULT: MC1-MC2 (MC2.70 MC2B.30), MC3 (J10.2)

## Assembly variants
Default: not fitted M1 M2 MC1A MC1B MC1C MC1D MC2A MC2B MC2C MC2D R7 R14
